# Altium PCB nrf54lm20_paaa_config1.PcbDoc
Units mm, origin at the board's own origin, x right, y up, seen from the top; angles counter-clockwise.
Board outline 13.12 x 12 mm, 8 copper layers (Top Side, Mid-Layer 1, Mid-Layer 2, Mid-Layer 3, Mid-Layer 4, Mid-Layer 5, Mid-Layer 6, Bottom Side), stack 1.529 mm thick; 24 components, 87 nets, 146 pads, 236 vias.
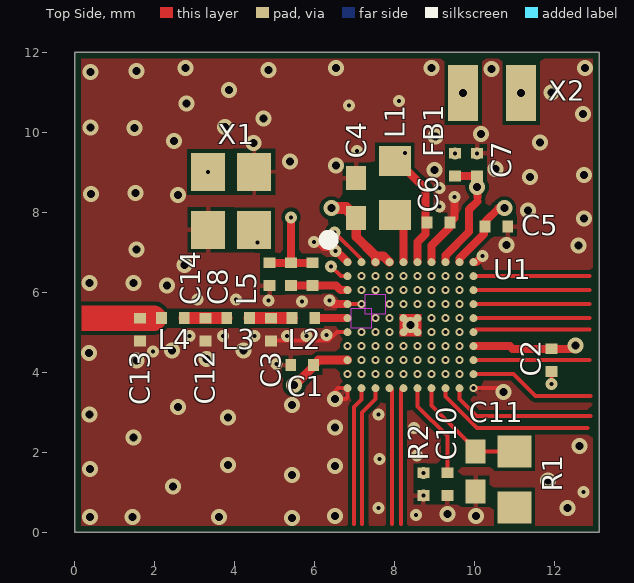
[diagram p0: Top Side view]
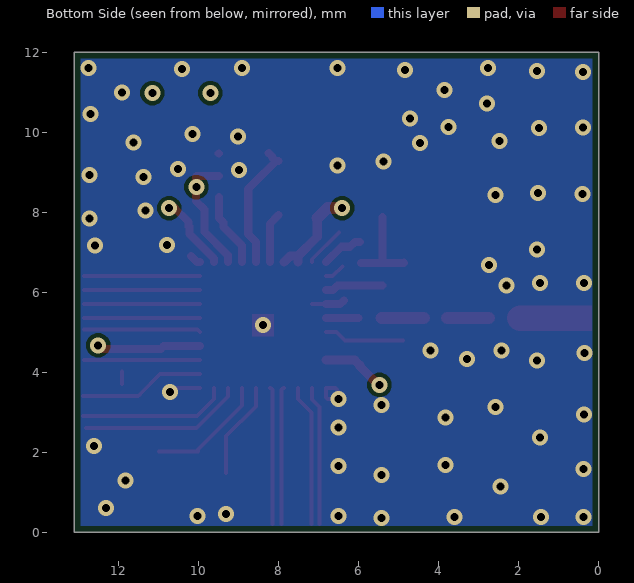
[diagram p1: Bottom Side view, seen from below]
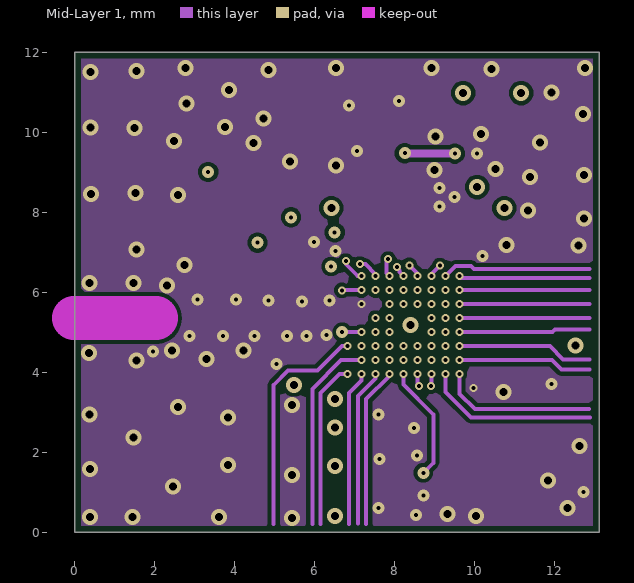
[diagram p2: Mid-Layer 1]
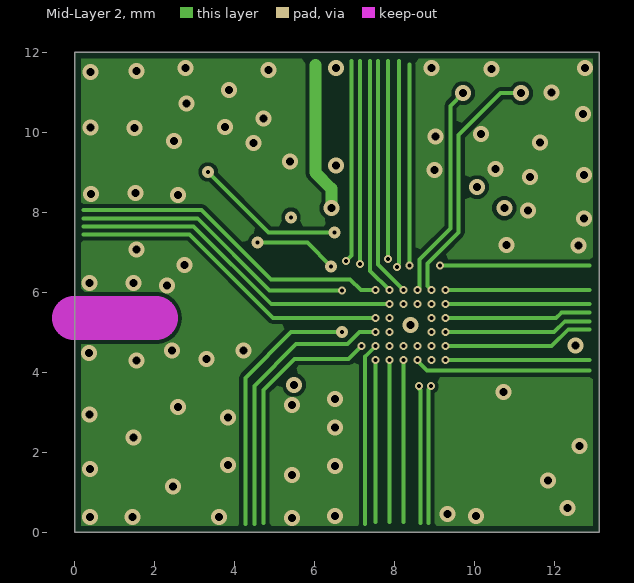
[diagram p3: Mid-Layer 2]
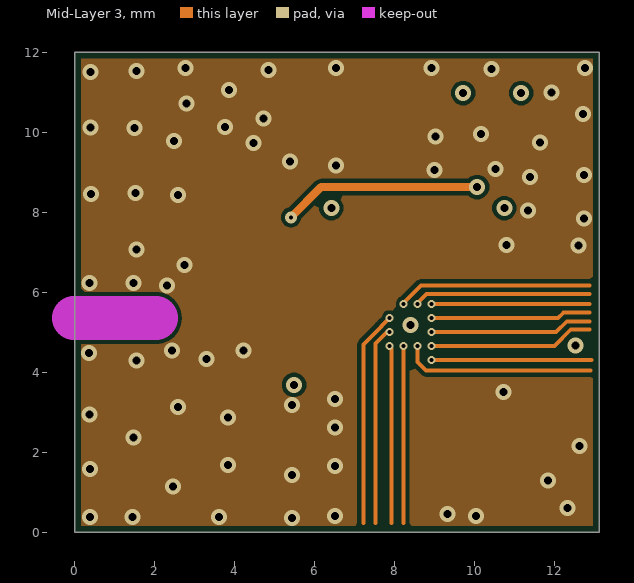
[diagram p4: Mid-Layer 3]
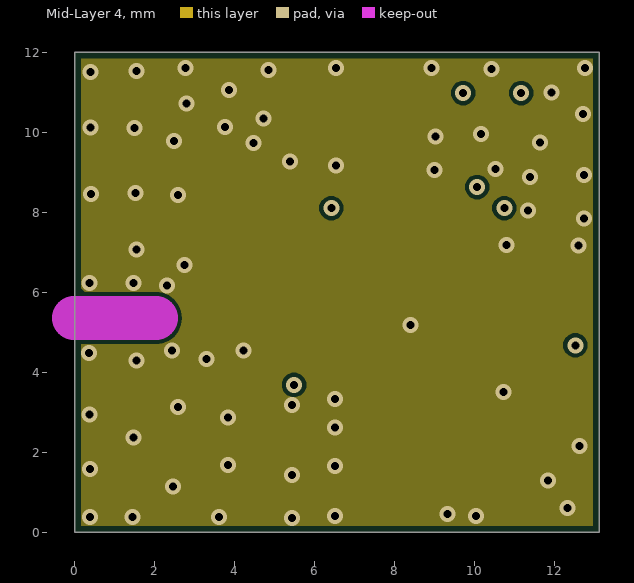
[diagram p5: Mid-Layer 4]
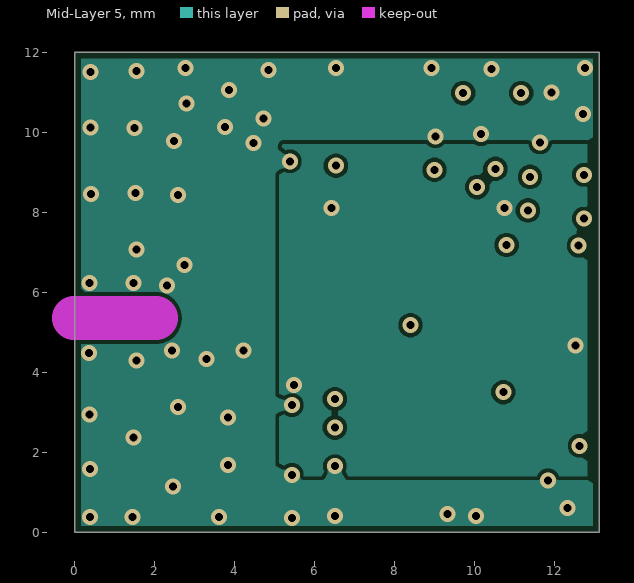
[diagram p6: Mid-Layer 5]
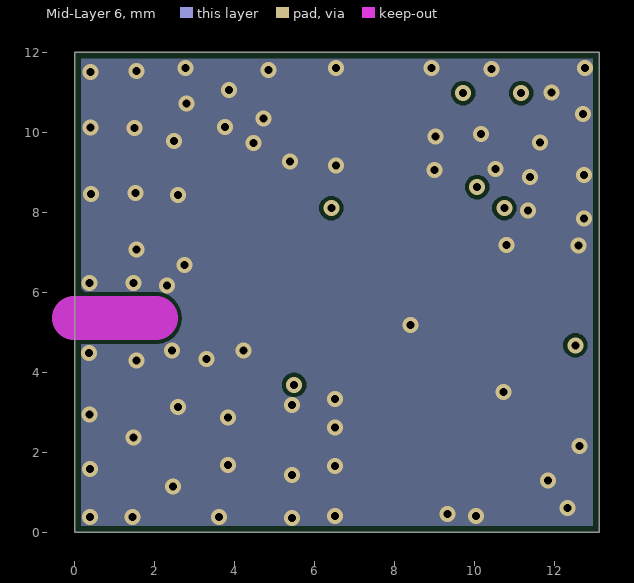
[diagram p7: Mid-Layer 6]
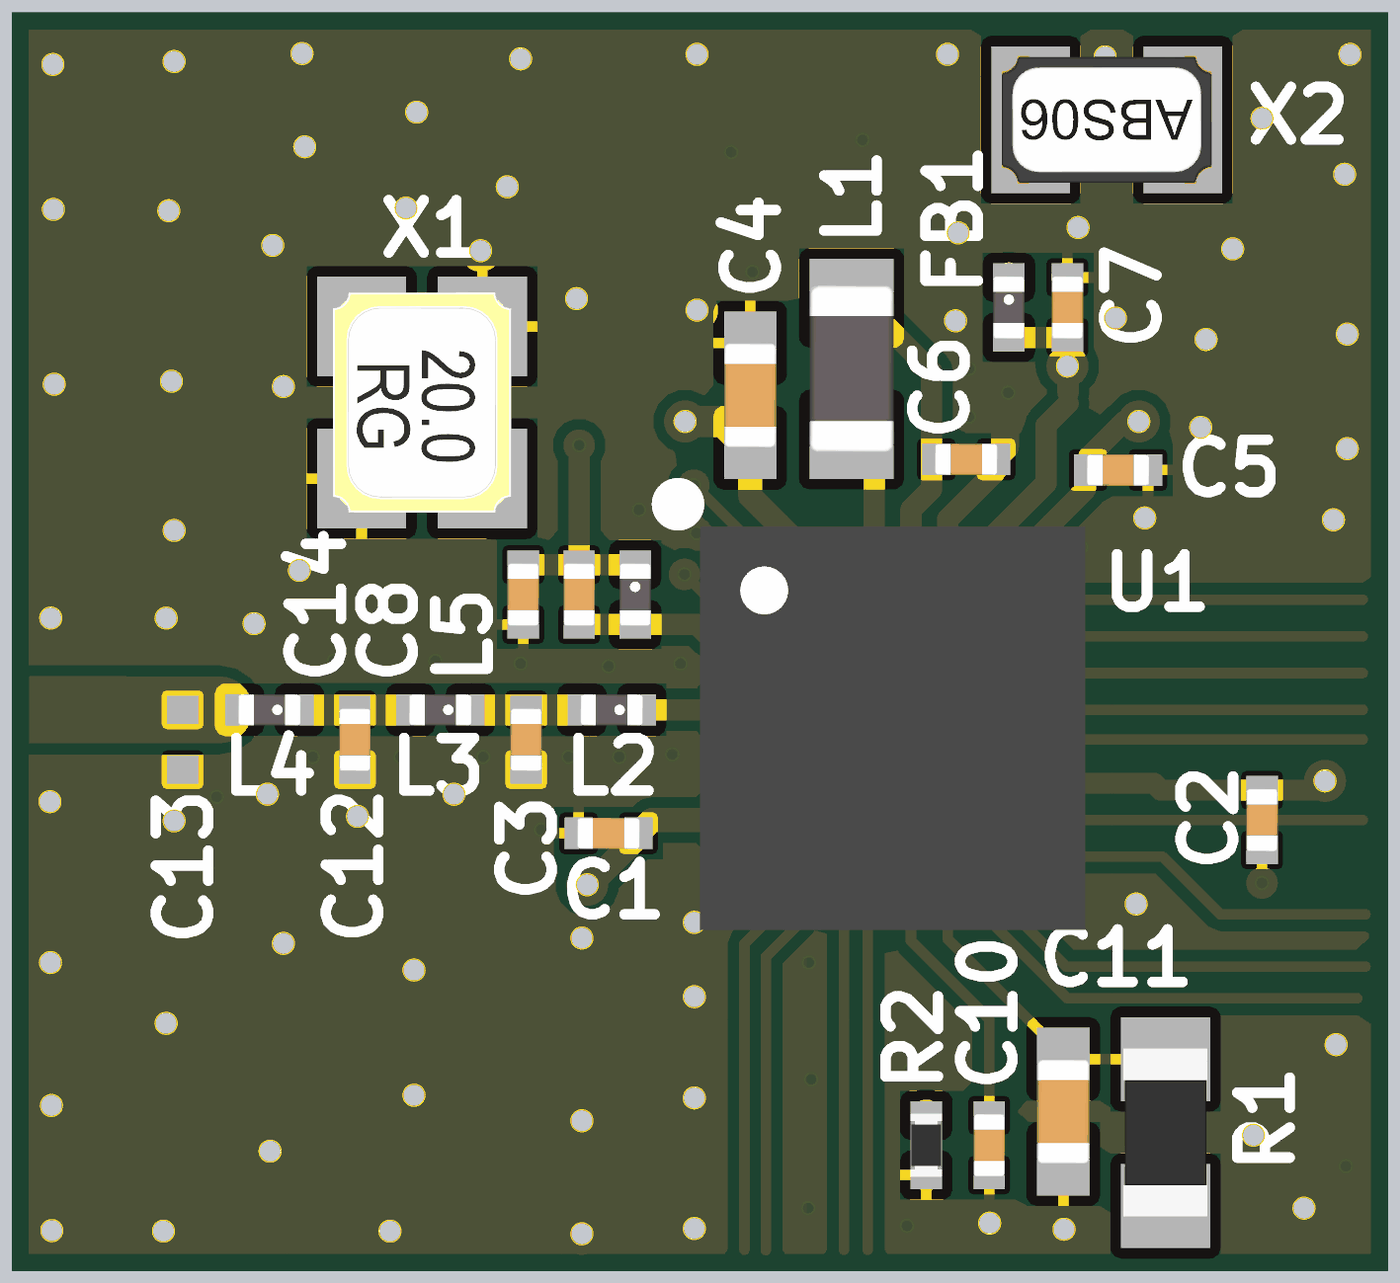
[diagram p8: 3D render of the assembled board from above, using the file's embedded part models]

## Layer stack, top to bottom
Top Solder: solder mask 0.015, WE-SM-0001, Dk 3.3
Top Side: signal copper 0.035
Dielectric 1: prepreg 0.07, WE-PP-0034, Dk 4.3
Mid-Layer 1: signal copper 0.025
Dielectric 2: prepreg 0.07, WE-PP-0034, Dk 4.3
Mid-Layer 2: signal copper 0.025
Dielectric 3: prepreg 0.07, WE-PP-0034, Dk 4.3
Mid-Layer 3: signal copper 0.025
Core 1: core 0.889, Core-041, Dk 4.8
Mid-Layer 4: signal copper 0.025
Dielectric 4: prepreg 0.07, WE-PP-0034, Dk 4.3
Mid-Layer 5: signal copper 0.025
Dielectric 5: prepreg 0.07, WE-PP-0034, Dk 4.3
Mid-Layer 6: signal copper 0.025
Dielectric 6: prepreg 0.07, WE-PP-0034, Dk 4.3
Bottom Side: signal copper 0.035
Bottom Solder: solder mask 0.015, WE-SM-0001, Dk 3.3

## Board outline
0,0 13.118,0 13.118,12 0,12

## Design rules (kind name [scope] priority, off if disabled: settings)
BoardOutlineClearance [All] p1: gap=0.15 ignorepadtopadclearanceinfootprint=FALSE except(0: Arc-SplitContinuation Track-SplitContinuation SMDPad-SplitContinuation THPad-SplitContinuation Via-SplitContinuation Fill-SplitContinuation Poly-SplitContinuation Region-SplitContinuation Text-SplitContinuation)
Clearance Clearance_1 [All] p1: gap=0.099 ignorepadtopadclearanceinfootprint=TRUE
Clearance RF_Clearance [InNetClass('RF')] p2: gap=0.15 ignorepadtopadclearanceinfootprint=FALSE
Clearance [All] p3: gap=0.1 ignorepadtopadclearanceinfootprint=TRUE
DiffPairsRouting NFC [InDifferentialPairClass('NFC')] p1: maxlimit=0.15 minlimit=0.1 mostfreqgap=0.1 toplayer_minwidth=0.09 toplayer_maxwidth=0.2 toplayer_prefwidth=0.1 midlayer1_minwidth=0.09 midlayer1_maxwidth=0.2 midlayer1_prefwidth=0.1 midlayer2_minwidth=0.09 midlayer2_maxwidth=0.2 midlayer2_prefwidth=0.1 midlayer3_minwidth=0.09 midlayer3_maxwidth=0.2 midlayer3_prefwidth=0.1 midlayer4_minwidth=0.09 midlayer4_maxwidth=0.2 midlayer4_prefwidth=0.1 midlayer5_minwidth=0.09 midlayer5_maxwidth=0.2 midlayer5_prefwidth=0.1 midlayer6_minwidth=0.09 midlayer6_maxwidth=0.2 midlayer6_prefwidth=0.1 bottomlayer_minwidth=0.09 bottomlayer_maxwidth=0.2 bottomlayer_prefwidth=0.1 maxuncoupledlength=12.7
DiffPairsRouting USB [InDifferentialPairClass('USB')] p2: maxlimit=0.127 minlimit=0.127 mostfreqgap=0.127 toplayer_minwidth=0.099 toplayer_maxwidth=0.099 toplayer_prefwidth=0.099 midlayer1_minwidth=0.049 midlayer1_maxwidth=0.049 midlayer1_prefwidth=0.049 midlayer2_minwidth=0.049 midlayer2_maxwidth=0.049 midlayer2_prefwidth=0.049 midlayer3_minwidth=0.07 midlayer3_maxwidth=0.07 midlayer3_prefwidth=0.07 midlayer4_minwidth=0.049 midlayer4_maxwidth=0.049 midlayer4_prefwidth=0.049 midlayer5_minwidth=0.07 midlayer5_maxwidth=0.07 midlayer5_prefwidth=0.07 midlayer6_minwidth=0.049 midlayer6_maxwidth=0.049 midlayer6_prefwidth=0.049 bottomlayer_minwidth=0.105 bottomlayer_maxwidth=0.105 bottomlayer_prefwidth=0.105 impedanceprofiledriven=TRUE maxuncoupledlength=12.7
DiffPairsRouting [All] p3: maxlimit=0.254 minlimit=0.254 mostfreqgap=0.254 toplayer_minwidth=0.381 toplayer_maxwidth=0.381 toplayer_prefwidth=0.381 midlayer1_minwidth=0.381 midlayer1_maxwidth=0.381 midlayer1_prefwidth=0.381 midlayer2_minwidth=0.381 midlayer2_maxwidth=0.381 midlayer2_prefwidth=0.381 midlayer3_minwidth=0.381 midlayer3_maxwidth=0.381 midlayer3_prefwidth=0.381 midlayer4_minwidth=0.381 midlayer4_maxwidth=0.381 midlayer4_prefwidth=0.381 midlayer5_minwidth=0.381 midlayer5_maxwidth=0.381 midlayer5_prefwidth=0.381 midlayer6_minwidth=0.381 midlayer6_maxwidth=0.381 midlayer6_prefwidth=0.381 bottomlayer_minwidth=0.381 bottomlayer_maxwidth=0.381 bottomlayer_prefwidth=0.381 maxuncoupledlength=12.7
HoleSize [All] p1: absolutevalues=TRUE maxlimit=2.54 minlimit=0.1 maxpercent=80.000 minpercent=20.000
HoleToHoleClearance [All] p1 off: gap=0.254 allowstackedmicrovias=TRUE
PlaneClearance [All] p1: clearance=0.1
PlaneConnect [All] p1: planeconnectstyle=Relief reliefexpansion=0.2 reliefentries=4 reliefconductorwidth=0.2 reliefairgap=0.1
PolygonConnect POWER [IsVia and (InNet('GND') or InNet('VDD_nRF'))] p1: connectstyle=Direct reliefconductorwidth=0.254 reliefentries=4 polygonreliefangle="90 Angle" airgapwidth=0.254
PolygonConnect PolygonConnect_RF [InComponent('C3') or InComponent('C12') or InComponent('C13')] p2: connectstyle=Direct reliefconductorwidth=0.1 reliefentries=4 polygonreliefangle="90 Angle" airgapwidth=0.1
PolygonConnect [All] p3: connectstyle=Relief reliefconductorwidth=0.1 reliefentries=4 polygonreliefangle="90 Angle" conductorbypadedge=TRUE mindistance=0.2 enablemindistance=FALSE airgapwidth=0.1
RoutingVias [All] p1: holewidth=0.711 width=1.27 viastyle="Through Hole" minholewidth=0.711 minwidth=1.27 maxholewidth=0.711 maxwidth=1.27 useviatemplates=TRUE viatemplateguid#1={2D42D20E-691A-49BE-AF35-B9B90945E0E8} viatemplateguid#2={DFC61F4A-0A20-4448-BCAE-CDEF2102FAEA} viatemplateguid#3={62FB19A3-6431-40EB-8EAC-CC177D510BB4} viatemplatename#1=v20h10m0 viatemplatename#2=v30h10m0 viatemplatename#3=v40h20m0mx0
SolderMaskExpansion [All] p1: expansion=0.102 istentingtop=FALSE
SupplyNets "Schematic Supply Nets_2" [InNet('GND')] p1: voltage=0.000
SupplyNets "Schematic Supply Nets_1" [InNet('VBUS')] p2: voltage=0.000
SupplyNets "Schematic Supply Nets" [InNet('VDD_nRF')] p3: voltage=0.000
Width RF [InNetClass('RF')] p1: maxlimit=0.735 minlimit=0.1 preferedwidth=0.1 toplayer_prefwidth=0.735 midlayer1_maxwidth=0.2 midlayer2_maxwidth=0.2 midlayer3_maxwidth=0.2 midlayer4_maxwidth=0.2 midlayer5_maxwidth=0.2 midlayer6_maxwidth=0.2 bottomlayer_maxwidth=0.2 minimp=50.000000 maximp=50.000000 favimp=50.000000 checkconnectedcopper=TRUE
Width [All] p2: maxlimit=1 minlimit=0.095 preferedwidth=0.152
25 further rules are at their usual default settings.

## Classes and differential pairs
differential pair class NFC: NFC
differential pair class USB: USB_D
differential pair NFC: +NFC_P -NFC_N
differential pair USB_D: +USB_D_P -USB_D_N

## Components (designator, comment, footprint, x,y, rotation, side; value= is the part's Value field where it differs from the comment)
C1 "100nF" CAPC0603X03L_C 5.69,4.174 r180 top
C2 "100nF" CAPC0603X03L_C 11.918,4.3 r270 top
C3 "1.2pF" CAPC0603X03L_C 4.904,5.066 r90 top
C4 "10µF" CAPC1005X04L 7.04,8.349 r270 top
C5 "100nF" CAPC0603X03L_C 10.546,7.638 r0 top
C6 "4.7µF" CAPC0603X03L_C 9.098,7.739 r180 top
C7 "2.2µF" CAPC0603X03L_C 10.064,9.187 r270 top
C8 "1.0pF" CAPC0603X03L_C 5.41,6.449 r90 top
C10 "2.2µF" CAPC0603X03L_C 9.318,1.2 r90 top
C11 "4.7µF" CAPC1005X04L 10.024,1.521 r90 top
C12 "1.5pF" CAPC0603X03L_C 3.272,5.066 r270 top
C13 "N.C." CAPC0603X03L_C_NC 1.631,5.066 r90 top
C14 "2.2µF" CAPC0603X03L_C 4.877,6.449 r90 top
FB1 "120R/0.2A" INDC0603X03L_C 9.505,9.187 r270 top
L1 "4.7µH" INDC1608X06L 8.006,8.603 r90 top
L2 "3.6nH" INDC0603X03L_C 5.72,5.351 r180 top
L3 "4.7nH" INDC0603X03L_C 4.087,5.351 r180 top
L4 "3.3nH" INDC0603X03L_C 2.459,5.351 r180 top
L5 "1.0nH" INDC0603X03L_C 5.943,6.449 r270 top
R1 "2R2" RESC1608X06L 10.998,1.321 r270 top
R2 "200R" RESC0603X03L_C 8.718,1.2 r90 top
U1 "nRF54LM20-PAAA-BE0" BGA98C35P10X10_367X385X86 8.397,5.176 r0 top
X1 "32MHz" BT-XTAL_2016 3.912,8.28 r270 top
X2 "32.768kHz" XTAL_2012 10.439,10.977 r180 top

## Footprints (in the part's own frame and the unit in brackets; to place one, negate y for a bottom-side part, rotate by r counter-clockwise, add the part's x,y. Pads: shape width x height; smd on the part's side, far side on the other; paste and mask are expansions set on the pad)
BGA98C35P10X10_367X385X86 [mm] "BGA, 98-Leads, Body 3.67x3.85mmx0.86mm, Pitch 0.35mm"
  round 0.2 smd: A1(-1.575,1.575) A2(-1.225,1.575) A3(-0.875,1.575) A4(-0.525,1.575) A5(-0.175,1.575) A6(0.175,1.575) A7(0.525,1.575) A8(0.875,1.575) A9(1.225,1.575) A10(1.575,1.575) B1(-1.575,1.225) B2(-1.225,1.225) B3(-0.875,1.225) B4(-0.525,1.225) B5(-0.175,1.225) B6(0.175,1.225) B7(0.525,1.225) B8(0.875,1.225) B9(1.225,1.225) B10(1.575,1.225) C1(-1.575,0.875) C2(-1.225,0.875) C3(-0.875,0.875) C4(-0.525,0.875) C5(-0.175,0.875) C6(0.175,0.875) C7(0.525,0.875) C8(0.875,0.875) C9(1.225,0.875) C10(1.575,0.875) D1(-1.575,0.525) D2(-1.225,0.525) D4(-0.525,0.525) D5(-0.175,0.525) D6(0.175,0.525) D7(0.525,0.525) D8(0.875,0.525) D9(1.225,0.525) D10(1.575,0.525) E1(-1.575,0.175) E3(-0.875,0.175) E4(-0.525,0.175) E5(-0.175,0.175) E6(0.175,0.175) E7(0.525,0.175) E8(0.875,0.175) E9(1.225,0.175) E10(1.575,0.175) F1(-1.575,-0.175) F2(-1.225,-0.175) F3(-0.875,-0.175) F4(-0.525,-0.175) F5(-0.175,-0.175) F6(0.175,-0.175) F7(0.525,-0.175) F8(0.875,-0.175) F9(1.225,-0.175) F10(1.575,-0.175) G1(-1.575,-0.525) G2(-1.225,-0.525) G3(-0.875,-0.525) G4(-0.525,-0.525) G5(-0.175,-0.525) G6(0.175,-0.525) G7(0.525,-0.525) G8(0.875,-0.525) G9(1.225,-0.525) G10(1.575,-0.525) H1(-1.575,-0.875) H2(-1.225,-0.875) H3(-0.875,-0.875) H4(-0.525,-0.875) H5(-0.175,-0.875) H6(0.175,-0.875) H7(0.525,-0.875) H8(0.875,-0.875) H9(1.225,-0.875) H10(1.575,-0.875) J1(-1.575,-1.225) J2(-1.225,-1.225) J3(-0.875,-1.225) J4(-0.525,-1.225) J5(-0.175,-1.225) J6(0.175,-1.225) J7(0.525,-1.225) J8(0.875,-1.225) J9(1.225,-1.225) J10(1.575,-1.225) K1(-1.575,-1.575) K2(-1.225,-1.575) K3(-0.875,-1.575) K4(-0.525,-1.575) K5(-0.175,-1.575) K6(0.175,-1.575) K7(0.525,-1.575) K8(0.875,-1.575) K9(1.225,-1.575) K10(1.575,-1.575)
  Top Side keep-out region: -1.125,0.775 -0.625,0.775 -0.625,0.275 -1.125,0.275
  Top Side keep-out region: -1.475,0.425 -0.975,0.425 -0.975,-0.075 -1.475,-0.075
  silkscreen extent -2.17,2.01 -1.92,2.26, body extent -1.84,-1.92 1.84,1.92, height 0.86
BT-XTAL_2016 [mm] "Crystal 2.0 x 1.6 mm"
  rect 0.95x0.85 smd: 1(-0.725,-0.575) 2(0.725,-0.575) 3(0.725,0.575) 4(-0.725,0.575)
  body extent -1.05,-0.85 1.05,0.85, height 0.56
CAPC0603X03L_C [mm] "Chip Capacitor, 2-Leads, Body 0.6x0.3mm, IPC High Density"
  rect 0.27x0.3 smd mask+0.05: 1(-0.285,0) 2(0.285,0)
  body extent -0.3,-0.15 0.3,0.15, height 0.3
CAPC0603X03L_C_NC [mm] "Chip Capacitor, 2-Leads, Body 0.6x0.3mm, IPC High Density"
  rect 0.27x0.3 smd mask+0.05: 1(-0.285,0) 2(0.285,0)
CAPC1005X04L [mm] "Chip Capacitor, 2-Leads, Body 1.0x0.5mm, IPC High Density"
  rect 0.6x0.5 smd: 1(-0.5,0) 2(0.5,0)
  body extent -0.5,-0.25 0.5,0.25, height 0.5
INDC0603X03L_C [mm] "Chip Inductor, 2-Leads, Body 0.6x0.3mm, IPC High Density"
  rect 0.27x0.3 smd: 1(-0.285,0) 2(0.285,0)
  body extent -0.3,-0.15 0.3,0.15, height 0.3
INDC1608X06L [mm] "Chip Inductor, 2-Leads, Body 1.6x0.8mm, IPC High Density"
  rect 0.75x0.8 smd: 1(-0.675,0) 2(0.675,0)
  body extent -0.8,-0.4 0.8,0.4, height 0.8
RESC0603X03L_C [mm] "Chip Resistor, 2-Leads, Body 0.6x0.3mm, IPC High Density"
  rect 0.27x0.3 smd: 1(-0.285,0) 2(0.285,0)
  body extent -0.3,-0.15 0.3,0.15, height 0.23
RESC1608X06L [mm] "Chip Resistor, 2-Leads, Body 1.6x0.8mm, IPC High Density"
  rect 0.8x0.85 smd: 1(-0.7,0) 2(0.7,0)
  body extent -0.8,-0.4 0.8,0.4, height 0.4
XTAL_2012 [mm] "XTAL SMD 2.0 x 1.2 mm"
  rect 0.75x1.4 smd: 1(-0.725,0) 2(0.725,0)
  body extent -1,-0.61 1,0.61, height 0.6

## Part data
C1 C2 C5: library part C0201-100n-10V-X7R, "Capacitor, X7R, ±10%", Manufacturer=N.A., Part number NEMS=100200469
C3: library part C0201-1.2p-HQ-Murata, "Capacitor, NP0, ±0.05pF, 50V", Manufacturer=Murata, Manufacturer Part Number=GJM0335C1H1R2WB01D, Part number IPS=N.A., Part number NEMS=100200457, Supplier Part Number 1=490-GJM0335C1H1R2WB01DCT-ND
C4: library part C0402-10µF-6.3V-X6S, "Capacitor, X6S, ±20%, 6.3V", Manufacturer=N.A., Part number NEMS=100200478
C6: library part C0201-4.7µ-6V3-X5R-GRM035R60J475ME15J, "Capacitor, Ceramic, X5R, ±20%, 6.3V", Manufacturer=Murata, Manufacturer Part Number=GRM035R60J475ME15J, Part number IPS=N.A., Part number NEMS=100200685, Supplier Part Number 1=490-GRM035R60J475ME15JDKR-ND
C7 C14: library part C0201-2µ2-2.5V-X6T-GRM033D80E225ME47D, "Capacitor, Ceramic, 2.2µF 2.5V X6T 0201,±20%", Manufacturer=Murata, Manufacturer Part Number=GRM033D80E225ME47D, Part number IPS=N.A., Part number NEMS=100200527, Supplier Part Number 1=81-GRM033D80E225ME7D
C8: library part C0201-1p0-25V-COG-GJM0335C1E1R0WB01, "CAP CER 1.0PF 25V C0G/NP0 0201", Manufacturer=Murata, Manufacturer Part Number=GJM0335C1E1R0WB01, Part number IPS=N.A., Part number NEMS=100200676, Supplier Part Number 1=490-10677-1-ND
C10: library part C0201-2µ2-2.5V-X6T-GRM033D80E225ME47D, "Capacitor, Ceramic, 2.2µF 2.5V X6T 0201,±20%", Manufacturer=Murata, Manufacturer Part Number=GRM033R61A225KE47, Part number IPS=N.A., Part number NEMS=100200527, Supplier Part Number 1=81-GRM033D80E225ME7D
C11: library part C0402-4µ7-10V-X5R, "Capacitor, X5R, 10V", Manufacturer=Murata, Manufacturer Part Number=GRM155R61A475MEAAD, Part number IPS=N.A., Part number NEMS=100200415, Supplier Part Number 1=490-14306-1-ND
C12: library part C0201-1.5p-25V-NP0-GJM0335C1E1R5WB01, "Capacitor, NP0, ±0.05pF, 25V, High Q", Manufacturer=Murata, Manufacturer Part Number=GJM0335C1E1R5WB01, Part number IPS=N.A., Part number NEMS=100200477, Supplier Part Number 1=490-11176-2-ND
C13: library part C0201-N.C., "Not mounted", Manufacturer=N.A., Part number NEMS=100200001
FB1: library part FB0201-120R@100M-200mA-BLM03AG121SN1D, "Ferrite Bead, 120 Ohm @ 100MHz, 200mA, 500 mOhm Max", Manufacturer=Murata, Manufacturer Part Number=BLM03AG121SN1D, Part number IPS=N.A., Part number NEMS=100300419, Supplier Part Number 1=490-5622-1-ND
L1: library part L0603-4µ7-MLZ1608M4R7WT000, "Inductor, 120mA, ±20%, 0.65R", Manufacturer="TDK Corporation", Manufacturer Part Number=MLZ1608M4R7WT000, Part number IPS=N.A., Part number NEMS=100300440, Supplier Part Number 1=445-6390-2-ND
L2: library part L0201-3n6-HQ-Murata, "Inductor, 500mA, ±0.1ｎH, 170mOhm", Manufacturer=Murata, Manufacturer Part Number=LQP03HQ3N6B02, Part number IPS=N.A., Part number NEMS=100300223, Supplier Part Number 1=490-13927-1-ND
L3: library part L0201-4n7-HQ-Murata, "Inductor, 400mA, ±3%, 250mOhm", Manufacturer=Murata, Manufacturer Part Number=LQP03HQ4N7H02, Part number IPS=N.A., Part number NEMS=100300231, Supplier Part Number 1=490-13943-1-ND
L4: library part L0201-3n3-HQ-Murata, "Inductor, 500mA, ±0.1ｎH, 170mOhm", Manufacturer=Murata, Manufacturer Part Number=LQP03HQ3N3B02, Part number IPS=N.A., Part number NEMS=100300220, Supplier Part Number 1=490-13921-1-ND
L5: library part L0201-1n0, "Inductor, 750mA, ±0.2nH", Manufacturer=Murata, Manufacturer Part Number=LQP03TN1N0C02D, Part number IPS=N.A., Part number NEMS=100300012, Supplier Part Number 1=490-5546-1-ND
R1: library part R0603-2R2, "RES 2.2 OHM 1% 1/10W 0603", Manufacturer=N.A.
R2: library part R0201-200, "Resistor, ±1%, 0.05W", Manufacturer=N.A., Part number NEMS=100100611
U1: "nRF54 series BLE", Manufacturer="Nordic Semiconductor", Part number IPS=N.A., Part number NEMS=102000483
X1: library part XTAL_SMD2016_32MHz_8pF_Kyocera, "XTAL SMD 2016, 32MHz, Cl=8pF, Tot: ±40ppm", Manufacturer=Kyocera, Manufacturer Part Number=CX2016DB32000D0WZRC1, Part number IPS=00000007827, Part number NEMS=101600039, Part number Norautron=26511136, Supplier Part Number 1=1253-1586-1-ND
X2: library part XTAL_SMD2012_32.768kHz_9pF_TXC, "XTAL SMD 2012, 32.768kHz, 9pF, ±20ppm", Manufacturer="TXC Corporation", Manufacturer Part Number=9HT11-32.768KDZC-T, Part number IPS=N.A., Part number NEMS=101600107, Supplier Part Number 1=887-1426-2-ND

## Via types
v1: diameter 0.4, hole 0.2, Top Side to Bottom Side, tented both sides, 75 vias
v2: diameter 0.2, hole 0.1, Top Side to Mid-Layer 1, tented top, 61 vias
v3: diameter 0.3, hole 0.1, Top Side to Mid-Layer 1, tented top, 40 vias
v4: diameter 0.2, hole 0.1, Mid-Layer 1 to Mid-Layer 2, 36 vias
v5: diameter 0.2, hole 0.1, Mid-Layer 2 to Mid-Layer 3, tented top, 12 vias
v6: diameter 0.2, hole 0.1, Mid-Layer 1 to Mid-Layer 2, tented top, 5 vias
v7: diameter 0.3, hole 0.1, Mid-Layer 1 to Mid-Layer 2, tented top, 4 vias
v8: diameter 0.3, hole 0.1, Mid-Layer 1 to Mid-Layer 2, 2 vias
v9: diameter 0.3, hole 0.1, Mid-Layer 2 to Mid-Layer 3, 1 vias

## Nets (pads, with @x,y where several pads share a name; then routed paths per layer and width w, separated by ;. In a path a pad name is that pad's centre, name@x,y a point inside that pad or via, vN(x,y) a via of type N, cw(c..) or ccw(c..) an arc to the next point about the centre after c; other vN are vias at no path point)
ant:1: L2.1 U1.E1 | length 0.8
  Top Side w0.2: L2.1@6.007,5.351 U1.E1
ant:2: C3.2 L2.2 L3.1 | length 1.1
  Top Side w0.3: L3.1 L2.2
ant:3: C12.1 L3.2 L4.1 | length 1.1
  Top Side w0.3: L4.1 L3.2
ant:4: C13.2 L4.2 | length 1.3
  Top Side w0.635: 0.681,5.351 1.981,5.351
DCC: L1.1 U1.A5 | length 1.3
  Top Side w0.203: L1.1 8.222,7.712 U1.A5
DECA: C7.2 C8.2 C14.2 FB1.2 L5.1 U1.A8 | length 10.1
  Top Side w0.203: C14.2@4.877,6.737 4.879,6.734 L5.1 ; C8.2 v9(5.41,7.873) ; U1.A8 9.272,6.922 9.86,7.511 9.86,8.064 10.069,8.273 ; FB1.2 C7.2 10.069,8.896 10.069,8.374
  Mid-Layer 3 w0.203: v9(5.41,7.873) 6.165,8.628 v1(10.064,8.628)
  other v3: 5.41,7.873
  other v8: 5.41,7.873
DECD: C6.2 FB1.1 L1.2 U1.A6 | length 4.4
  Top Side w0.203: L1.2 8.068,9.278 8.618,8.728 8.768,8.577 8.768,7.456 8.572,7.259 U1.A6 ; L1.2@8.159,9.354 8.159,9.378 v3(8.255,9.474) ; v3(9.505,9.466) FB1.1
  Mid-Layer 1 w0.203: v3(8.255,9.474) 8.263,9.466 v3(9.505,9.466)
DECRF: C8.1 L5.2 U1.C1 | length 1.5
  Top Side w0.203: C8.1 L5.2 6.536,6.164 6.649,6.051 U1.C1
GND: C1.2 C2.2 C3.1 C4.1 C5.2 C6.1 C7.1 C10.1 C11.1 C12.2 C13.1 C14.1 R2.1 U1.A1 U1.A7 U1.A10 U1.D1 U1.D2 U1.E5 U1.E6 U1.F1 U1.F5 U1.F6 U1.K1 U1.K10 X1.2 X1.4 | length 8.5
  Top Side w0.1: C3.1@4.904,4.79 6.348,4.79 v3@6.426,4.868 ; 6.486,4.929 v3@6.426,4.868 ; U1.F1 6.558,5.001 v3@6.426,4.868 ; U1.D1 v2(7.172,5.701) ; v2(9.972,3.601) 10.617,3.601 v1(10.718,3.5) ccw(c10.474,3.256) v1@10.606,3.575 ; v3(11.918,3.7) C2.2 ; v1(6.507,3.325) 6.779,3.325 6.822,3.368 U1.K1 6.588,3.601 6.507,3.521 v1(6.507,3.325)
  Top Side w0.203: v3(5.98,7.259) 6.102,7.259 6.223,7.137 6.436,7.137 U1.A1 ; v3(6.375,5.791) 6.466,5.701 U1.D1 ; U1.A7 8.922,7.169 9.383,7.631 C6.1 9.499,7.855 v3(9.499,8.374) ; U1.A10 10.045,6.751 v3(10.194,6.9)
  other v1: 5.436,0.356 1.448,0.381 3.607,0.381 0.384,0.386 6.507,0.406 10.031,0.399 9.322,0.457 12.318,0.6 2.464,1.143 11.836,1.295 5.436,1.433 0.38,1.579 6.507,1.651 3.835,1.676 12.624,2.159 1.473,2.362 6.507,2.616 3.835,2.87 0.371,2.941 2.591,3.124 5.436,3.175 1.549,4.293 3.297,4.335 0.366,4.475 2.438,4.547 4.216,4.547 8.397,5.176 2.311,6.172 0.373,6.226 1.473,6.226 2.743,6.68 1.549,7.061 12.598,7.163 10.8,7.18 12.731,7.841 11.334,8.044 2.591,8.433 0.406,8.456 1.524,8.484 11.384,8.882 12.731,8.933 8.997,9.06 10.521,9.085 6.533,9.162 5.385,9.271 4.47,9.728 11.638,9.746 2.489,9.779 9.022,9.898 10.165,9.949 1.499,10.109 0.399,10.122 3.759,10.135 4.724,10.338 12.705,10.457 2.794,10.719 11.918,10.99 3.861,11.049 0.394,11.504 1.549,11.532 4.851,11.557 10.423,11.577 2.769,11.608 6.533,11.6 8.921,11.6 12.756,11.6
  other v3: 8.534,0.432 7.593,0.6 8.718,0.915 12.718,1 7.62,1.829 8.565,1.915 8.489,2.608 7.598,2.941 5.047,4.208 1.956,4.521 2.87,4.902 3.708,4.902 4.496,4.902 5.309,4.902 5.791,4.902 6.297,4.926 5.69,5.766 4.851,5.791 3.073,5.817 4.039,5.817 6.528,7.036 9.124,8.146 9.124,8.603 10.058,9.472 7.061,9.525 6.858,10.668 8.11,10.785
NetC11_2: C11.2 R1.1 U1.K7 | length 3.1
  Top Side w0.1: U1.K7 8.922,3.168 10.024,2.067 C11.2 10.503,2.021 ; 10.457,2.021 10.503,2.021 ; R1.1 10.503,2.021
NFC_N: U1.J6 | length 3.8
  Mid-Layer 1 w0.1: v2(8.572,3.951) 8.572,3.695 v4(8.607,3.659)
  Mid-Layer 2 w0.1: v4(8.607,3.659) 8.628,3.638 8.628,3.569 8.645,3.552 8.645,0.229
NFC_P: U1.J7 | length 3.8
  Mid-Layer 1 w0.09: v4(8.907,3.651) ccw(c8.872,3.687) v4@8.922,3.687
  Mid-Layer 1 w0.1: v4@8.922,3.687 v2(8.922,3.951)
  Mid-Layer 2 w0.1: 8.848,0.229 8.848,3.563 8.907,3.621 v4(8.907,3.651)
NRESET: U1.F2 | length 7
  Mid-Layer 1 w0.1: v8(6.69,5.001) v2(7.172,5.001)
  Mid-Layer 2 w0.1: 4.267,0.2 4.267,3.861 5.407,5.001 v8(6.69,5.001)
P0.00: U1.K3 | length 3.5
  Top Side w0.1: 7.188,0.2 7.188,2.997 7.522,3.331 U1.K3
P0.01: U1.K2 | length 3.5
  Top Side w0.1: 6.985,0.203 6.985,3.125 7.172,3.312 U1.K2
P0.02: U1.J3 | length 3.9
  Mid-Layer 1 w0.1: 7.087,0.215 7.087,3.407 7.522,3.842 v2(7.522,3.951)
P0.03: U1.J2 | length 3.9
  Mid-Layer 1 w0.1: 6.858,0.201 6.858,3.48 7.174,3.796 7.174,3.949 v2(7.172,3.951)
P0.04: U1.J1 | length 4.1
  Mid-Layer 1 w0.1: 6.147,0.21 6.147,3.48 6.618,3.951 v2(6.822,3.951)
P0.05: U1.H3 | length 4
  Mid-Layer 2 w0.1: 7.522,0.256 v2(7.522,4.301)
  other v6: 7.522,4.301
P0.06: U1.H2 | length 4.9
  Mid-Layer 1 w0.1: 5.944,0.2 5.944,3.581 6.663,4.301 v2(7.172,4.301)
P0.07: U1.G3 | length 4.6
  Mid-Layer 2 w0.095: 7.264,4.396 v4@7.522,4.648
  Mid-Layer 2 w0.1: 7.264,0.203 7.264,4.396
  other v2: 7.522,4.651
  other v4: 7.522,4.651
P0.08: U1.F3 | length 7
  Mid-Layer 2 w0.1: 4.496,0.203 4.496,3.658 5.537,4.699 6.82,4.699 7.122,5.001 v2(7.522,5.001)
  other v4: 7.522,5.001
P0.09: U1.E3 | length 8.2
  Mid-Layer 2 w0.1: 0.221,7.442 2.878,7.442 4.965,5.356 7.124,5.356 v2(7.522,5.351)
  other v4: 7.522,5.351
P1.00: U1.K8 | length 4.1
  Top Side w0.1: U1.K8 9.272,3.392 10.064,2.6 12.825,2.6
P1.03: U1.H9 | length 3.4
  Mid-Layer 1 w0.1: v2(9.622,4.301) 11.93,4.301 12.167,4.064 12.878,4.064
P1.04: U1.J9 | length 3.9
  Mid-Layer 1 w0.1: v2(9.622,3.951) 9.622,3.459 10.006,3.075 12.858,3.075
P1.05: U1.H8 | length 3.6
  Mid-Layer 1 w0.1: v2(9.272,4.301) v4@9.295,4.324
  Mid-Layer 2 w0.1: v4@9.28,4.301 v2(9.272,4.301) 12.878,4.301
  other v4: 9.272,4.301
P1.06: U1.J8 | length 4.3
  Mid-Layer 1 w0.1: v2(9.272,3.951) 9.272,3.504 9.906,2.87 12.89,2.87
P1.07: U1.G8 | length 3.8
  Mid-Layer 2 w0.1: v2(9.272,4.651) 11.925,4.651 12.347,5.074 12.878,5.074
  other v4: 9.272,4.651
P1.08: U1.F8 | length 3.7
  Mid-Layer 2 w0.1: v2(9.272,5.001) 11.986,5.001 12.259,5.274 12.878,5.274
  other v4: 9.272,5.001
P1.09: U1.E8 | length 3.7
  Mid-Layer 2 w0.1: v2(9.272,5.351) 12.031,5.351 12.167,5.486 12.878,5.486
  other v4: 9.272,5.351
P1.10: U1.D5 | length 4.9
  Mid-Layer 3 w0.1: v2(8.222,5.701) 8.222,5.733 8.661,6.172 12.878,6.172
  other v4: 8.222,5.701
  other v5: 8.222,5.701
P1.11: U1.C5 | length 6
  Mid-Layer 2 w0.1: 7.59,11.786 7.59,6.687 8.222,6.055 v2(8.222,6.051)
  other v4: 8.222,6.051
P1.12: U1.C4 | length 5.9
  Mid-Layer 2 w0.1: 7.39,11.786 7.39,6.533 v2(7.872,6.051)
  other v4: 7.872,6.051
P1.13: U1.C3 | length 8.1
  Mid-Layer 1 w0.1: v4(7.518,6.05) v2(7.522,6.051) v2(7.522,6.051)
  Mid-Layer 2 w0.1: 0.221,8.052 3.175,8.052 4.905,6.322 6.884,6.322 7.156,6.05 v4(7.518,6.05)
P1.14: U1.C2 | length 7.7
  Mid-Layer 1 w0.1: v4(6.68,6.045) 6.686,6.051 v2(7.172,6.051)
  Mid-Layer 2 w0.1: 0.221,7.849 3.073,7.849 4.877,6.045 v4(6.68,6.045)
P1.15: U1.B2 | length 5.7
  Mid-Layer 1 w0.1: v4(6.781,6.779) 6.781,6.699 7.079,6.401 v2@7.159,6.401 ; v2@7.159,6.401 v2(7.172,6.401) v2@7.159,6.401
  Mid-Layer 2 w0.1: v4@6.781,6.787 v4(6.781,6.779) 6.918,6.916 6.918,11.786
P1.16: U1.B3 | length 5.6
  Mid-Layer 1 w0.1: v4(7.132,6.701) 7.269,6.701 7.522,6.448 v2(7.522,6.401)
  Mid-Layer 2 w0.1: v4(7.132,6.701) 7.132,11.786
P1.17: U1.B4 | length 5.4
  Mid-Layer 1 w0.1: v4(7.84,6.829) 7.798,6.787 7.798,6.475 7.855,6.417 v2(7.872,6.401)
  Mid-Layer 2 w0.1: v4(7.84,6.829) 7.84,11.786
P1.18: U1.B5 | length 5.5
  Mid-Layer 1 w0.1: v4(8.065,6.631) 8.061,6.627 8.12,6.544 ; 8.122,6.541 8.122,6.501 v2(8.222,6.401)
  Mid-Layer 2 w0.1: v4@8.084,6.65 v4(8.065,6.631) ccw(c7.957,6.739) 8.11,6.739 8.11,11.786
P1.19: U1.B6 | length 5.4
  Mid-Layer 1 w0.1: v4(8.368,6.672) 8.572,6.468 v2(8.572,6.401)
  Mid-Layer 2 w0.1: v4(8.368,6.672) 8.368,11.688
P1.22: U1.D6 | length 4.4
  Mid-Layer 3 w0.1: v2(8.572,5.701) 8.572,5.727 8.796,5.951 12.878,5.951
  other v4: 8.572,5.701
  other v5: 8.572,5.701
P1.23: U1.B7 | length 4.1
  Mid-Layer 1 w0.1: v2(8.922,6.401) 8.922,6.457 v4(9.13,6.665)
  Mid-Layer 2 w0.1: v4(9.13,6.665) 12.878,6.665
P1.24: U1.D7 | length 4
  Mid-Layer 3 w0.1: v2(8.922,5.701) 12.878,5.701
  other v4: 8.922,5.701
  other v5: 8.922,5.701
P1.25: U1.E7 | length 4
  Mid-Layer 3 w0.1: v2(8.922,5.351) 12.082,5.351 12.217,5.486 12.878,5.486
  other v4: 8.922,5.351
  other v5: 8.922,5.351
P1.26: U1.B8 | length 3.7
  Mid-Layer 1 w0.1: v2(9.272,6.401) 9.272,6.41 9.517,6.655 9.906,6.655 9.982,6.579 12.878,6.579
P1.27: U1.C8 | length 3.7
  Mid-Layer 2 w0.1: v2(9.272,6.051) 12.289,6.051 ; 12.363,6.051 12.289,6.051 ; 12.878,6.051 12.289,6.051
  other v4: 9.272,6.051
P1.28: U1.D8 | length 3.6
  Mid-Layer 2 w0.1: v2(9.272,5.701) 12.878,5.701
  other v4: 9.272,5.701
P1.29: U1.H10 | length 2.9
  Top Side w0.1: U1.H10 12.878,4.3
P1.30: U1.J10 | length 3.2
  Top Side w0.1: U1.J10 10.967,3.951 11.492,3.426 11.518,3.4 12.903,3.4
P1.31: U1.K9 | length 3.7
  Top Side w0.1: U1.K9 9.622,3.332 10.051,2.903 12.903,2.903
P2.00: U1.B10 | length 2.9
  Top Side w0.1: U1.B10 12.878,6.401
P2.01: U1.C10 | length 2.9
  Top Side w0.1: U1.C10 12.878,6.051
P2.02: U1.D10 | length 2.9
  Top Side w0.1: U1.D10 12.878,5.701
P2.03: U1.E10 | length 2.9
  Top Side w0.1: U1.E10 12.878,5.351
P2.04: U1.F10 | length 2.9
  Top Side w0.1: U1.F10 10.039,5.069 12.878,5.069
P2.05: U1.G9 | length 3.4
  Mid-Layer 1 w0.1: v2(9.622,4.651) 11.882,4.651 12.215,4.318 12.878,4.318
P2.06: U1.B9 | length 3.3
  Mid-Layer 1 w0.1: v2(9.622,6.401) 9.673,6.35 12.878,6.35
P2.07: U1.C9 | length 3.3
  Mid-Layer 1 w0.1: v2(9.622,6.051) 12.878,6.051
P2.08: U1.D9 | length 3.3
  Mid-Layer 1 w0.1: v2(9.622,5.701) 12.878,5.701
P2.09: U1.E9 | length 3.3
  Mid-Layer 1 w0.1: v2(9.622,5.351) 12.878,5.351
P2.10: U1.F9 | length 3.3
  Mid-Layer 1 w0.1: v2(9.622,5.001) 11.941,5.001 12.009,5.069 12.878,5.069
P3.00: U1.H7 | length 4
  Mid-Layer 3 w0.1: v2(8.922,4.301) 12.918,4.301
  other v5: 8.922,4.301
  other v6: 8.922,4.301
P3.01: U1.H6 | length 4.4
  Mid-Layer 2 w0.1: v2(8.572,4.301) 8.572,4.28 8.814,4.039 12.878,4.039
  other v6: 8.572,4.301
P3.02: U1.H5 | length 4
  Mid-Layer 2 w0.1: 8.222,0.256 8.222,4.209 v2(8.222,4.301)
  other v6: 8.222,4.301
P3.03: U1.H4 | length 4
  Mid-Layer 2 w0.1: 7.872,0.256 7.872,4.24 v2(7.872,4.301)
  other v6: 7.872,4.301
P3.04: U1.J4 | length 4
  Mid-Layer 1 w0.1: 7.29,0.201 7.29,3.327 7.872,3.91 v2(7.872,3.951)
P3.05: U1.G7 | length 4.1
  Mid-Layer 3 w0.1: v2(8.922,4.651) 11.992,4.651 12.414,5.074 12.878,5.074
  other v4: 8.922,4.651
  other v5: 8.922,4.651
P3.06: U1.G6 | length 4.8
  Mid-Layer 3 w0.1: v5@8.578,4.65 8.572,4.644 8.572,4.255 8.787,4.04 12.903,4.04
  other v2: 8.572,4.651
  other v4: 8.572,4.651
  other v5: 8.572,4.651
P3.07: U1.G5 | length 4.4
  Mid-Layer 3 w0.1: 8.222,0.229 v2(8.222,4.651)
  other v4: 8.222,4.651
  other v5: 8.222,4.651
P3.08: U1.G4 | length 4.4
  Mid-Layer 3 w0.1: v2(7.872,4.651) 7.872,4.624 7.918,4.578 7.918,0.229
  other v4: 7.872,4.651
  other v5: 7.872,4.651
P3.09: U1.F7 | length 4.1
  Mid-Layer 3 w0.1: v2(8.922,5.001) 12.037,5.001 12.309,5.274 12.878,5.274
  other v4: 8.922,5.001
  other v5: 8.922,5.001
P3.10: U1.F4 | length 5
  Mid-Layer 3 w0.1: 7.518,0.229 7.518,4.714 7.773,4.969 cw(c7.844,4.899) 7.829,4.998 cw(c7.872,4.716) v2(7.872,5.001)
  other v4: 7.872,5.001
  other v5: 7.872,5.001
P3.11: U1.E4 | length 5.4
  Mid-Layer 3 w0.1: 7.218,0.229 7.218,4.697 7.668,5.147 ccw(c7.597,5.217) 7.675,5.155 cw(c7.872,5.001) 7.697,5.18 v2(7.872,5.351)
  other v4: 7.872,5.351
  other v5: 7.872,5.351
P3.12: U1.D4 | length 8.5
  Mid-Layer 2 w0.1: 0.221,7.645 2.972,7.645 4.916,5.701 v2(7.872,5.701)
  other v4: 7.872,5.701
SWDCLK: U1.G1 | length 5.7
  Mid-Layer 1 w0.1: 4.978,0.2 4.978,3.683 5.338,4.043 6.075,4.043 6.683,4.651 v2(6.822,4.651)
SWDIO: U1.G2 | length 6.2
  Mid-Layer 2 w0.1: 4.718,0.229 4.718,3.55 5.499,4.33 6.851,4.33 v2(7.172,4.651)
  other v4: 7.172,4.651
TRXTUNE: R2.2 U1.J5 | length 2.9
  Mid-Layer 1 w0.1: v2(8.222,3.951) 8.222,3.691 8.966,2.946 8.966,1.733 v3(8.718,1.485)
USB_D_N: U1.K4 | length 3.4
  Top Side w0.099: U1.K4 cw(c7.872,3.539) 7.934,3.539 7.934,0.203
USB_D_P: U1.K5 | length 3.4
  Top Side w0.099: 8.16,0.203 8.16,3.539 cw(c8.222,3.539) U1.K5
VBUS: R1.2
VDD_nRF: C1.1 C2.1 C4.2 C5.1 U1.A3 U1.A4 U1.A9 U1.G10 U1.H1 | length 12.3
  Top Side w0.2: C4.2@7.04,7.59 C4.2@7.04,7.671 ; U1.A4 U1.A4@7.872,6.758 ; U1.A9 9.622,6.84 10.236,7.454 C5.1@10.236,7.638 ; U1.G10 10.887,4.651 10.953,4.585 12.435,4.585 12.518,4.668 v1(12.518,4.674) ; C5.1 10.261,7.759 10.602,8.1 v1(10.744,8.1)
  Top Side w0.229: v1@5.512,3.683 5.969,4.14 C1.1@5.969,4.158 ; C1.1 6.102,4.301 U1.H1 ; C4.2 7.04,7.59 7.04,7.387 7.522,6.905 ; U1.A3 7.522,6.905 ; U1.A4 7.718,6.905 7.522,6.905
  Top Side w0.3: v1(6.418,8.1) 6.789,8.1 C4.2
  Mid-Layer 2 w0.3: 6.018,11.679 6.018,8.991 6.418,8.591 v1(6.418,8.1)
  other v1: 5.486,3.683
VDD_USB_3V3: C10.2 U1.K6 | length 2.5
  Top Side w0.1: U1.K6 8.572,3.147 9.318,2.401 9.318,1.778 ; C10.2 9.318,1.778 ; 9.318,1.859 9.318,1.778
XC1: U1.A2 X1.1 | length 4.8
  Top Side w0.1: v3(6.502,7.493) 7.172,6.823 U1.A2
  Mid-Layer 2 w0.1: v3(3.337,9.005) 4.849,7.493 v3(6.502,7.493)
  other v7: 6.502,7.493 3.337,9.005
XC2: U1.B1 X1.3 | length 2.6
  Top Side w0.1: v3(6.413,6.642) 6.655,6.401 U1.B1
  Mid-Layer 2 w0.1: v7(4.572,7.239) 5.817,7.239 v3(6.413,6.642)
  other v3: 4.572,7.239
  other v7: 6.413,6.642
XL1: U1.C6 X2.2 | length 5.4
  Mid-Layer 2 w0.1: v2(8.572,6.051) 8.618,6.097 8.618,6.364 8.618,6.815 9.398,7.595 9.398,10.661 v1(9.714,10.977)
  other v4: 8.572,6.051
XL2: U1.C7 X2.1 | length 6.2
  Mid-Layer 2 w0.1: v4@8.922,6.053 v2(8.922,6.051) 8.822,6.151 8.822,6.717 9.601,7.496 9.601,9.931 10.647,10.977 v1(11.164,10.977)
  other v4: 8.922,6.051

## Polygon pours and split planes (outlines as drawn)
GND on Mid-Layer 5 "NONET_L-01_P-001" (solid, remove dead copper, pour order 8): 0,12 13.118,12 13.118,0 0,0
VDD_nRF on Mid-Layer 5 "NONET_L-01_P-001" (solid, remove dead copper, pour order 6): 5.118,9.7 12.818,9.7 12.818,1.4 5.118,1.4
GND on Mid-Layer 4 "NONET_L-01_P-001" (solid, remove dead copper, pour order 0): 0,12 13.118,12 13.118,0 0,0
GND on Mid-Layer 2 "NONET_L-01_P-001" (solid, remove dead copper, pour order 3): 0,12 13.118,12 13.118,0 0,0
GND on Bottom Side "NONET_L-01_P-001" (solid, remove dead copper, pour order 4): 0,12 13.118,12 13.118,0 0,0
GND on Mid-Layer 3 "NONET_L-01_P-001" (solid, remove dead copper, pour order 5): 0,12 13.118,12 13.118,0 0,0
GND on Mid-Layer 6 "NONET_L-01_P-001" (solid, remove dead copper, pour order 7): 0,12 13.118,12 13.118,0 0,0
GND on Mid-Layer 1 "NONET_L-01_P-001" (solid, remove dead copper, pour order 10): 0,12 13.118,12 13.118,0 0,0
GND on Top Side "NONET_L-01_P-001" (solid, remove dead copper, pour order 2): 0,12 13.118,12 13.118,0 0,0

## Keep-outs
Mid-Layer 1:
  lines w1.1: -0.01,5.351 2.038,5.351
Mid-Layer 2:
  lines w1.1: -0.01,5.351 2.038,5.351
Mid-Layer 3:
  lines w1.1: -0.01,5.351 2.038,5.351
Mid-Layer 6:
  lines w1.1: -0.01,5.351 2.038,5.351
Mid-Layer 4:
  lines w1.1: -0.01,5.351 2.038,5.351
Mid-Layer 5:
  lines w1.1: -0.01,5.351 2.038,5.351

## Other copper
Top Side:
  region net ant:4: 1.094,5.032 1.094,5.671 0.168,5.671 0.168,5.032
  rectangle net GND: 8.122,4.894 8.672,5.451

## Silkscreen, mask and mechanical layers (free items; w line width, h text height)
Board Outline:
  the board outline again, w0.1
